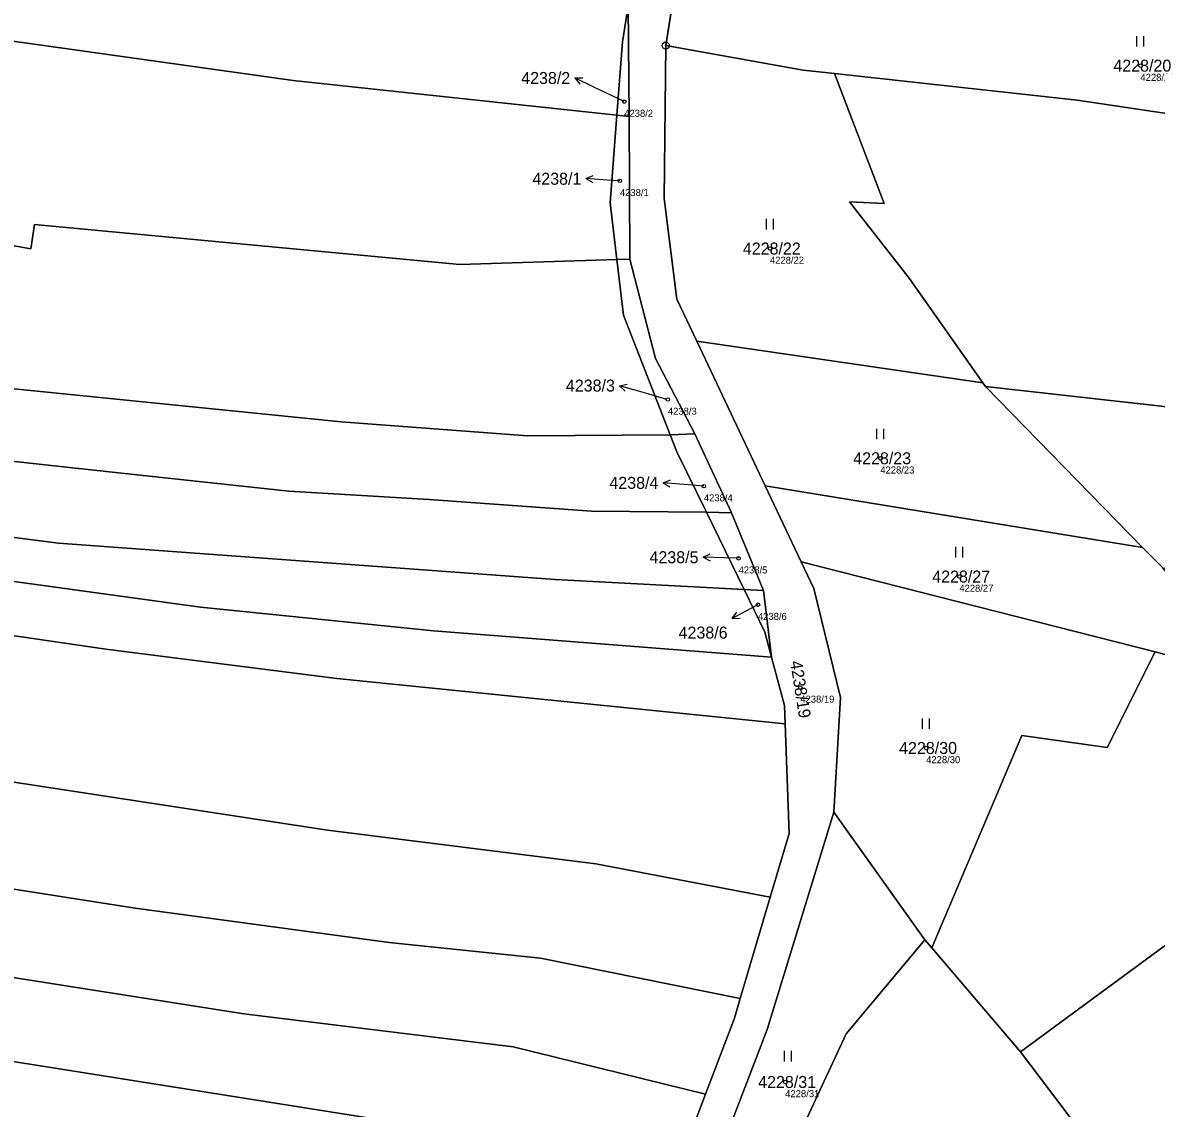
# Model space of a CAD drawing. Extents: x -739214 to -733252, y -1147612 to -1142842.
# Drawn here: x -736874.9 to -736714.1, y -1146796.7 to -1146642.6 of the extents above; entities that cross this region are included whole.
import ezdxf

# ---------------------------------------------------------------- set-up
doc = ezdxf.new("R2010")
doc.units = 0
for name, color, linetype in [('Definiční body', 7, 'Continuous'), ('Hranice parcel', 7, 'Continuous'), ('Parcelní čísla', 7, 'Continuous'), ('Polygon parcely', 7, 'Continuous'), ('Pop  PČ popisy', 7, 'Continuous'), ('Značky bodu BP', 7, 'Continuous'), ('Značky kultur', 7, 'Continuous')]:
    doc.layers.add(name, color=color, linetype=linetype)

msp = doc.modelspace()

# ---------------------------------------------------------------- linework, layer by layer
at = {"layer": 'Definiční body'}
for centre in [(-736716.31, -1146648.75), (-736789.55, -1146653.85), (-736790.17, -1146665.1), (-736768.88, -1146674.7), (-736783.36, -1146696.13), (-736753.22, -1146704.47), (-736778.25, -1146708.42), (-736773.33, -1146718.66), (-736742.01, -1146721.25), (-736770.58, -1146725.25), (-736764.57, -1146736.99), (-736746.71, -1146745.58), (-736766.71, -1146792.98)]:
    msp.add_circle(centre, 0.25, dxfattribs=at)
at = {"layer": 'Hranice parcel'}
for p, q in [((-736781.32, -1146630.98), (-736783.66, -1146645.9)), ((-736788.86, -1146655.98), (-736788.98, -1146640.27)), ((-736788.86, -1146655.98), (-736790.62, -1146655.79)), ((-736788.75, -1146676.19), (-736788.86, -1146655.98)), ((-736790.6, -1146676.25), (-736788.75, -1146676.19)), ((-736779.27, -1146687.87), (-736738.67, -1146693.74)), ((-736779.27, -1146687.87), (-736769.57, -1146708.36)), ((-736738.67, -1146693.74), (-736738.28, -1146694.29)), ((-736738.28, -1146694.29), (-736706.17, -1146697.87)), ((-736716.02, -1146717.12), (-736738.28, -1146694.29)), ((-736783.02, -1146701.16), (-736779.54, -1146701)), ((-736774.33, -1146712.22), (-736779.54, -1146701)), ((-736769.57, -1146708.36), (-736716.02, -1146717.12)), ((-736769.57, -1146708.36), (-736764.45, -1146719.17)), ((-736777.9, -1146712.12), (-736774.33, -1146712.22)), ((-736777.9, -1146712.12), (-736772.54, -1146723.09)), ((-736769.77, -1146723.24), (-736774.33, -1146712.22)), ((-736716.02, -1146717.12), (-736713.11, -1146720.03)), ((-736764.45, -1146719.17), (-736714.21, -1146731.96)), ((-736772.54, -1146723.09), (-736769.77, -1146723.24)), ((-736768.65, -1146732.68), (-736769.77, -1146723.24)), ((-736714.21, -1146731.96), (-736708.68, -1146733.4)), ((-736759.81, -1146754.71), (-736746.88, -1146772.8)), ((-736768.83, -1146766.73), (-736773.09, -1146781.12)), ((-736746.88, -1146772.8), (-736745.93, -1146773.92)), ((-736745.93, -1146773.92), (-736733.34, -1146788.69)), ((-736778.02, -1146794.7), (-736782.57, -1146806.7))]:
    msp.add_line(p, q, dxfattribs=at)
for points in [[(-736987.7, -1146616.21), (-736909.35, -1146638.55), (-736879.05, -1146644.89), (-736836.54, -1146650.87), (-736790.62, -1146655.79)], [(-736788.98, -1146640.27), (-736789.82, -1146645.38), (-736790.62, -1146655.79)], [(-736995.93, -1146643.63), (-736941.6, -1146660.97), (-736899.92, -1146670.08), (-736873.77, -1146674.75), (-736873.21, -1146671.3), (-736812.86, -1146676.97), (-736790.6, -1146676.25)], [(-736783.66, -1146645.9), (-736783.87, -1146667.62), (-736782.09, -1146681.9), (-736779.27, -1146687.87)], [(-736783.66, -1146645.9), (-736764.16, -1146649.39), (-736759.74, -1146649.84)], [(-736759.74, -1146649.84), (-736725.28, -1146653.64), (-736687.81, -1146659.24), (-736654.17, -1146663.69), (-736642.51, -1146664.84)], [(-736759.74, -1146649.84), (-736752.69, -1146668.3), (-736757.61, -1146668.07), (-736749.11, -1146678.93), (-736738.67, -1146693.74)], [(-736790.62, -1146655.79), (-736791.57, -1146668.24), (-736790.6, -1146676.25)], [(-737004.89, -1146662.68), (-736974.86, -1146673.36), (-736967.21, -1146676.02), (-736939.93, -1146683.05), (-736916.69, -1146688.12), (-736884.18, -1146693.81), (-736829.71, -1146699.31), (-736803.29, -1146701.29), (-736783.02, -1146701.16)], [(-737017.39, -1146669.38), (-736998.52, -1146677.08), (-736970.31, -1146686.77), (-736955.95, -1146690.85), (-736927.51, -1146696.9), (-736911.69, -1146699.77), (-736889.1, -1146703.51), (-736863.08, -1146706.36), (-736837.13, -1146709.13), (-736817.21, -1146710.34), (-736794.22, -1146711.99), (-736777.9, -1146712.12)], [(-736768.65, -1146732.68), (-736816.63, -1146728.98), (-736849.68, -1146725.58), (-736902.28, -1146718.37), (-736917.48, -1146716.04), (-736955.57, -1146709.21), (-736971.25, -1146705.04), (-737001.67, -1146695.16), (-737019.01, -1146687.71), (-737046.12, -1146671.4)], [(-737030.43, -1146673.64), (-737006.91, -1146684.57), (-736981.68, -1146695.02), (-736961.89, -1146700.69), (-736938.04, -1146706.02), (-736890.14, -1146713.91), (-736869.84, -1146716.5), (-736799.34, -1146721.69), (-736772.54, -1146723.09)], [(-736790.6, -1146676.25), (-736789.65, -1146684.15), (-736783.02, -1146701.16)], [(-736779.54, -1146701), (-736785.11, -1146690.33), (-736788.75, -1146676.19)], [(-737050.66, -1146676.64), (-737019.75, -1146696.06), (-737005.9, -1146701.69), (-736979.66, -1146710.05), (-736954.59, -1146716.81), (-736940.11, -1146719.06), (-736891.94, -1146727.36), (-736863.1, -1146731.57), (-736830.31, -1146735.7), (-736766.71, -1146742.16)], [(-736783.02, -1146701.16), (-736782.09, -1146703.55), (-736777.9, -1146712.12)], [(-736764.45, -1146719.17), (-736762.66, -1146722.96), (-736758.86, -1146738.4), (-736759.81, -1146754.71)], [(-736772.54, -1146723.09), (-736769.6, -1146729.13), (-736768.65, -1146732.68)], [(-736995.36, -1146731.12), (-736979.35, -1146732.67), (-736955.38, -1146736.79), (-736912.97, -1146744.79), (-736831.67, -1146757.24), (-736793.57, -1146762.03), (-736768.83, -1146766.73)], [(-736768.65, -1146732.68), (-736766.8, -1146739.53), (-736766.71, -1146742.16)], [(-736714.21, -1146731.96), (-736721.04, -1146745.5), (-736733.12, -1146743.82), (-736745.93, -1146773.92)], [(-736766.71, -1146742.16), (-736766.17, -1146757.71), (-736768.83, -1146766.73)], [(-736993.07, -1146750.37), (-736981.77, -1146747.79), (-736956.26, -1146753.1), (-736858.93, -1146768.32), (-736822.89, -1146773.18), (-736801.44, -1146775.41), (-736773.09, -1146781.12)], [(-736759.81, -1146754.71), (-736769.28, -1146785.51), (-736778.4, -1146809.32), (-736781.16, -1146819.55)], [(-736983.02, -1146760.31), (-736964.96, -1146764.19), (-736843.54, -1146783.31), (-736805.33, -1146787.97), (-736778.02, -1146794.7)], [(-736733.34, -1146788.69), (-736701.68, -1146765.42), (-736643.52, -1146838.85)], [(-736763.65, -1146798.14), (-736758.07, -1146786.13), (-736746.88, -1146772.8)], [(-736930.82, -1146781.07), (-736889.74, -1146787.96), (-736811.31, -1146800.41), (-736782.57, -1146806.7)], [(-736773.09, -1146781.12), (-736773.92, -1146783.91), (-736778.02, -1146794.7)], [(-736733.34, -1146788.69), (-736700, -1146832.77), (-736666.98, -1146874.57)]]:
    msp.add_lwpolyline(points, dxfattribs=at)
at = {"layer": 'Polygon parcely'}
for points in [[(-736778.4, -1146809.32), (-736769.28, -1146785.51), (-736759.81, -1146754.71), (-736758.86, -1146738.4), (-736762.66, -1146722.96), (-736764.45, -1146719.17), (-736769.57, -1146708.36), (-736779.27, -1146687.87), (-736782.09, -1146681.9), (-736783.87, -1146667.62), (-736783.66, -1146645.9), (-736781.32, -1146630.98), (-736769.74, -1146581.87), (-736759.31, -1146551.18)], [(-736768.92, -1146555.91), (-736770.76, -1146560.31), (-736774.35, -1146571.16), (-736776.76, -1146578.43), (-736777.99, -1146584.35), (-736782.32, -1146605.12), (-736784.45, -1146615.33), (-736786.49, -1146625.1), (-736788.98, -1146640.27), (-736788.86, -1146655.98), (-736788.75, -1146676.19), (-736785.11, -1146690.33), (-736779.54, -1146701), (-736774.33, -1146712.22), (-736769.77, -1146723.24), (-736768.65, -1146732.68), (-736766.8, -1146739.53), (-736766.71, -1146742.16), (-736766.17, -1146757.71), (-736768.83, -1146766.73), (-736773.09, -1146781.12), (-736773.92, -1146783.91), (-736778.02, -1146794.7), (-736782.57, -1146806.7)]]:
    msp.add_lwpolyline(points, dxfattribs=at)
for points in [[(-736790.62, -1146655.79), (-736789.82, -1146645.38), (-736788.98, -1146640.27), (-736857.43, -1146633.83), (-736876.47, -1146631.19), (-736891.85, -1146628.32), (-736933.71, -1146618.65), (-736984.03, -1146603.65), (-736987.7, -1146616.21), (-736909.35, -1146638.55), (-736879.05, -1146644.89), (-736836.54, -1146650.87)], [(-736873.21, -1146671.3), (-736812.86, -1146676.97), (-736790.6, -1146676.25), (-736791.57, -1146668.24), (-736790.62, -1146655.79), (-736836.54, -1146650.87), (-736879.05, -1146644.89), (-736909.35, -1146638.55), (-736987.7, -1146616.21), (-736995.93, -1146643.63), (-736941.6, -1146660.97), (-736899.92, -1146670.08), (-736873.77, -1146674.75)], [(-736654.17, -1146663.69), (-736642.51, -1146664.84), (-736644, -1146658.32), (-736650, -1146641.67), (-736690.49, -1146638.76), (-736764.83, -1146632.5), (-736781.32, -1146630.98), (-736783.66, -1146645.9), (-736764.16, -1146649.39), (-736759.74, -1146649.84), (-736725.28, -1146653.64), (-736687.81, -1146659.24)], [(-736790.62, -1146655.79), (-736788.86, -1146655.98), (-736788.98, -1146640.27), (-736789.82, -1146645.38)], [(-736967.21, -1146676.02), (-736939.93, -1146683.05), (-736916.69, -1146688.12), (-736884.18, -1146693.81), (-736829.71, -1146699.31), (-736803.29, -1146701.29), (-736783.02, -1146701.16), (-736789.65, -1146684.15), (-736790.6, -1146676.25), (-736812.86, -1146676.97), (-736873.21, -1146671.3), (-736873.77, -1146674.75), (-736899.92, -1146670.08), (-736941.6, -1146660.97), (-736995.93, -1146643.63), (-737004.89, -1146662.68), (-736974.86, -1146673.36)], [(-736738.67, -1146693.74), (-736749.11, -1146678.93), (-736757.61, -1146668.07), (-736752.69, -1146668.3), (-736759.74, -1146649.84), (-736764.16, -1146649.39), (-736783.66, -1146645.9), (-736783.87, -1146667.62), (-736782.09, -1146681.9), (-736779.27, -1146687.87)], [(-736749.11, -1146678.93), (-736738.67, -1146693.74), (-736738.28, -1146694.29), (-736706.17, -1146697.87), (-736685.25, -1146700.33), (-736639.62, -1146707.66), (-736640.07, -1146704.08), (-736642.53, -1146685.39), (-736642.51, -1146664.84), (-736654.17, -1146663.69), (-736687.81, -1146659.24), (-736725.28, -1146653.64), (-736759.74, -1146649.84), (-736752.69, -1146668.3), (-736757.61, -1146668.07)], [(-736791.57, -1146668.24), (-736790.6, -1146676.25), (-736788.75, -1146676.19), (-736788.86, -1146655.98), (-736790.62, -1146655.79)], [(-736970.31, -1146686.77), (-736955.95, -1146690.85), (-736927.51, -1146696.9), (-736911.69, -1146699.77), (-736889.1, -1146703.51), (-736863.08, -1146706.36), (-736837.13, -1146709.13), (-736817.21, -1146710.34), (-736794.22, -1146711.99), (-736777.9, -1146712.12), (-736782.09, -1146703.55), (-736783.02, -1146701.16), (-736803.29, -1146701.29), (-736829.71, -1146699.31), (-736884.18, -1146693.81), (-736916.69, -1146688.12), (-736939.93, -1146683.05), (-736967.21, -1146676.02), (-736974.86, -1146673.36), (-737004.89, -1146662.68), (-737017.39, -1146669.38), (-736998.52, -1146677.08)], [(-737042.86, -1146667.48), (-737043.08, -1146667.88), (-737046.12, -1146671.4), (-737019.01, -1146687.71), (-737001.67, -1146695.16), (-736971.25, -1146705.04), (-736955.57, -1146709.21), (-736917.48, -1146716.04), (-736902.28, -1146718.37), (-736849.68, -1146725.58), (-736816.63, -1146728.98), (-736768.65, -1146732.68), (-736769.6, -1146729.13), (-736772.54, -1146723.09), (-736799.34, -1146721.69), (-736869.84, -1146716.5), (-736890.14, -1146713.91), (-736938.04, -1146706.02), (-736961.89, -1146700.69), (-736981.68, -1146695.02), (-737006.91, -1146684.57), (-737030.43, -1146673.64), (-737033.1, -1146672.19)], [(-736938.04, -1146706.02), (-736890.14, -1146713.91), (-736869.84, -1146716.5), (-736799.34, -1146721.69), (-736772.54, -1146723.09), (-736777.9, -1146712.12), (-736794.22, -1146711.99), (-736817.21, -1146710.34), (-736837.13, -1146709.13), (-736863.08, -1146706.36), (-736889.1, -1146703.51), (-736911.69, -1146699.77), (-736927.51, -1146696.9), (-736955.95, -1146690.85), (-736970.31, -1146686.77), (-736998.52, -1146677.08), (-737017.39, -1146669.38), (-737030.43, -1146673.64), (-737006.91, -1146684.57), (-736981.68, -1146695.02), (-736961.89, -1146700.69)], [(-736766.71, -1146742.16), (-736766.8, -1146739.53), (-736768.65, -1146732.68), (-736816.63, -1146728.98), (-736849.68, -1146725.58), (-736902.28, -1146718.37), (-736917.48, -1146716.04), (-736955.57, -1146709.21), (-736971.25, -1146705.04), (-737001.67, -1146695.16), (-737019.01, -1146687.71), (-737046.12, -1146671.4), (-737050.66, -1146676.64), (-737019.75, -1146696.06), (-737005.9, -1146701.69), (-736979.66, -1146710.05), (-736954.59, -1146716.81), (-736940.11, -1146719.06), (-736891.94, -1146727.36), (-736863.1, -1146731.57), (-736830.31, -1146735.7)], [(-736783.02, -1146701.16), (-736779.54, -1146701), (-736785.11, -1146690.33), (-736788.75, -1146676.19), (-736790.6, -1146676.25), (-736789.65, -1146684.15)], [(-736831.67, -1146757.24), (-736793.57, -1146762.03), (-736768.83, -1146766.73), (-736766.17, -1146757.71), (-736766.71, -1146742.16), (-736830.31, -1146735.7), (-736863.1, -1146731.57), (-736891.94, -1146727.36), (-736940.11, -1146719.06), (-736954.59, -1146716.81), (-736979.66, -1146710.05), (-737005.9, -1146701.69), (-737019.75, -1146696.06), (-737050.66, -1146676.64), (-737052.19, -1146678.4), (-737068.74, -1146694.78), (-737052.08, -1146706.91), (-737033.19, -1146715.58), (-736995.36, -1146731.12), (-736979.35, -1146732.67), (-736955.38, -1146736.79), (-736912.97, -1146744.79)], [(-736769.57, -1146708.36), (-736716.02, -1146717.12), (-736738.28, -1146694.29), (-736738.67, -1146693.74), (-736779.27, -1146687.87)], [(-736687.49, -1146713.98), (-736697.11, -1146713.98), (-736706.17, -1146697.87), (-736738.28, -1146694.29), (-736716.02, -1146717.12), (-736713.11, -1146720.03), (-736687.16, -1146723.49)], [(-736777.9, -1146712.12), (-736774.33, -1146712.22), (-736779.54, -1146701), (-736783.02, -1146701.16), (-736782.09, -1146703.55)], [(-736705.95, -1146728.86), (-736713.11, -1146720.03), (-736716.02, -1146717.12), (-736769.57, -1146708.36), (-736764.45, -1146719.17), (-736714.21, -1146731.96), (-736708.68, -1146733.4)], [(-737082.85, -1146709.02), (-737093.68, -1146720.18), (-737094.09, -1146720.75), (-737066.42, -1146734.1), (-737040.41, -1146744.32), (-737010.63, -1146754.66), (-736986.58, -1146761.65), (-736983.02, -1146760.31), (-736964.96, -1146764.19), (-736843.54, -1146783.31), (-736805.33, -1146787.97), (-736778.02, -1146794.7), (-736773.92, -1146783.91), (-736773.09, -1146781.12), (-736801.44, -1146775.41), (-736822.89, -1146773.18), (-736858.93, -1146768.32), (-736956.26, -1146753.1), (-736981.77, -1146747.79), (-736993.07, -1146750.37), (-736994.95, -1146750.59), (-737011.4, -1146745.26), (-737026.74, -1146738.7), (-737060.19, -1146722.14)], [(-736772.54, -1146723.09), (-736769.77, -1146723.24), (-736774.33, -1146712.22), (-736777.9, -1146712.12)], [(-736759.81, -1146754.71), (-736746.88, -1146772.8), (-736745.93, -1146773.92), (-736733.12, -1146743.82), (-736721.04, -1146745.5), (-736714.21, -1146731.96), (-736764.45, -1146719.17), (-736762.66, -1146722.96), (-736758.86, -1146738.4)], [(-736768.65, -1146732.68), (-736769.77, -1146723.24), (-736772.54, -1146723.09), (-736769.6, -1146729.13)], [(-736858.93, -1146768.32), (-736822.89, -1146773.18), (-736801.44, -1146775.41), (-736773.09, -1146781.12), (-736768.83, -1146766.73), (-736793.57, -1146762.03), (-736831.67, -1146757.24), (-736912.97, -1146744.79), (-736955.38, -1146736.79), (-736979.35, -1146732.67), (-736995.36, -1146731.12), (-736993.07, -1146750.37), (-736981.77, -1146747.79), (-736956.26, -1146753.1)], [(-736647.58, -1146803.17), (-736638.39, -1146781.91), (-736637.03, -1146770.43), (-736651.86, -1146767.18), (-736676.64, -1146750.12), (-736695.55, -1146736.25), (-736708.68, -1146733.4), (-736714.21, -1146731.96), (-736721.04, -1146745.5), (-736733.12, -1146743.82), (-736745.93, -1146773.92), (-736733.34, -1146788.69), (-736701.68, -1146765.42), (-736643.52, -1146838.85), (-736648.54, -1146810.43)], [(-736769.28, -1146785.51), (-736778.4, -1146809.32), (-736781.16, -1146819.55), (-736775.63, -1146825.18), (-736763.65, -1146798.14), (-736758.07, -1146786.13), (-736746.88, -1146772.8), (-736759.81, -1146754.71)], [(-736930.82, -1146781.07), (-736889.74, -1146787.96), (-736811.31, -1146800.41), (-736782.57, -1146806.7), (-736778.02, -1146794.7), (-736805.33, -1146787.97), (-736843.54, -1146783.31), (-736964.96, -1146764.19), (-736983.02, -1146760.31), (-736979.78, -1146773.16), (-736955.54, -1146778.2)], [(-736700, -1146832.77), (-736666.98, -1146874.57), (-736660.7, -1146861.87), (-736653.24, -1146846.22), (-736643.52, -1146838.85), (-736701.68, -1146765.42), (-736733.34, -1146788.69)], [(-736674.01, -1146898.81), (-736669.44, -1146885.87), (-736666.98, -1146874.57), (-736700, -1146832.77), (-736733.34, -1146788.69), (-736745.93, -1146773.92), (-736746.88, -1146772.8), (-736758.07, -1146786.13), (-736763.65, -1146798.14), (-736728.64, -1146845.58), (-736715.25, -1146864.21), (-736681.73, -1146907.98)], [(-736924.76, -1146795.3), (-736862.24, -1146804.52), (-736813.67, -1146811.18), (-736785.96, -1146818.3), (-736782.9, -1146807.56), (-736782.57, -1146806.7), (-736811.31, -1146800.41), (-736889.74, -1146787.96), (-736930.82, -1146781.07)]]:
    msp.add_lwpolyline(points, close=True, dxfattribs=at)
at = {"layer": 'Pop  PČ popisy'}
for p, q in [((-736796.55, -1146650.47), (-736795.43, -1146650.46)), ((-736793.85, -1146651.79), (-736796.55, -1146650.47)), ((-736796.55, -1146650.47), (-736795.87, -1146651.36)), ((-736789.55, -1146653.85), (-736793.85, -1146651.79)), ((-736794.98, -1146664.78), (-736793.95, -1146664.35)), ((-736791.99, -1146664.99), (-736794.98, -1146664.78)), ((-736794.98, -1146664.78), (-736794.02, -1146665.35)), ((-736790.17, -1146665.1), (-736791.99, -1146664.99)), ((-736790.22, -1146694.17), (-736789.12, -1146693.97)), ((-736787.34, -1146695), (-736790.22, -1146694.17)), ((-736790.22, -1146694.17), (-736789.4, -1146694.93)), ((-736783.52, -1146696.13), (-736787.34, -1146695)), ((-736784.05, -1146707.94), (-736783.01, -1146707.53)), ((-736781.06, -1146708.2), (-736784.05, -1146707.94)), ((-736784.05, -1146707.94), (-736783.1, -1146708.53)), ((-736778.25, -1146708.42), (-736781.06, -1146708.2)), ((-736778.36, -1146718.5), (-736777.34, -1146718.03)), ((-736775.36, -1146718.6), (-736778.36, -1146718.5)), ((-736778.36, -1146718.5), (-736777.38, -1146719.03)), ((-736773.33, -1146718.66), (-736775.36, -1146718.6)), ((-736771.59, -1146725.8), (-736774.24, -1146727.21)), ((-736770.58, -1146725.25), (-736771.59, -1146725.8)), ((-736774.24, -1146727.21), (-736773.59, -1146726.3)), ((-736774.24, -1146727.21), (-736773.12, -1146727.18))]:
    msp.add_line(p, q, dxfattribs=at)
at = {"layer": 'Značky bodu BP'}
for radius in [0.5, 0.0303]:
    msp.add_circle((-736783.66, -1146645.9), radius, dxfattribs=at)
at = {"layer": 'Značky kultur'}
for p, q in [((-736716.82, -1146646.05), (-736716.82, -1146644.55)), ((-736715.82, -1146646.05), (-736715.82, -1146644.55)), ((-736769.39, -1146672), (-736769.39, -1146670.5)), ((-736768.39, -1146672), (-736768.39, -1146670.5)), ((-736753.73, -1146701.77), (-736753.73, -1146700.27)), ((-736752.73, -1146701.77), (-736752.73, -1146700.27)), ((-736742.52, -1146718.55), (-736742.52, -1146717.05)), ((-736741.52, -1146718.55), (-736741.52, -1146717.05)), ((-736747.22, -1146742.88), (-736747.22, -1146741.38)), ((-736746.22, -1146742.88), (-736746.22, -1146741.38)), ((-736766.8, -1146790.08), (-736766.8, -1146788.58)), ((-736765.8, -1146790.08), (-736765.8, -1146788.58))]:
    msp.add_line(p, q, dxfattribs=at)

# ---------------------------------------------------------------- texts
at = {"layer": 'Definiční body'}
for s, p in [('4228/20', (-736716.31, -1146650.91)), ('4238/2', (-736789.55, -1146656.01)), ('4238/1', (-736790.17, -1146667.26)), ('4228/22', (-736768.88, -1146676.86)), ('4238/3', (-736783.36, -1146698.29)), ('4228/23', (-736753.22, -1146706.63)), ('4238/4', (-736778.25, -1146710.58)), ('4238/5', (-736773.33, -1146720.82)), ('4228/27', (-736742.01, -1146723.41)), ('4238/6', (-736770.58, -1146727.41)), ('4238/19', (-736764.57, -1146739.15)), ('4228/30', (-736746.71, -1146747.74)), ('4228/31', (-736766.71, -1146795.14))]:
    msp.add_text(s, height=1, dxfattribs=at).set_placement(p)
at = {"layer": 'Parcelní čísla'}
for s, p in [('4228/20', (-736720.15, -1146649.6)), ('4238/2', (-736804.17, -1146651.35)), ('4238/1', (-736802.59, -1146665.65)), ('4228/22', (-736772.72, -1146675.55)), ('4238/3', (-736797.83, -1146695)), ('4228/23', (-736757.06, -1146705.32)), ('4238/4', (-736791.66, -1146708.81)), ('4238/5', (-736785.97, -1146719.36)), ('4228/27', (-736745.85, -1146722.1)), ('4238/6', (-736781.84, -1146730.06)), ('4228/30', (-736750.55, -1146746.43)), ('4228/31', (-736770.55, -1146793.83))]:
    msp.add_text(s, height=1.7, dxfattribs=at).set_placement(p)
msp.add_text('4238/19', height=1.7, rotation=279, dxfattribs=at).set_placement((-736766.01, -1146733.33))

doc.saveas('drawing.dxf')
